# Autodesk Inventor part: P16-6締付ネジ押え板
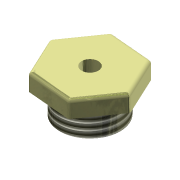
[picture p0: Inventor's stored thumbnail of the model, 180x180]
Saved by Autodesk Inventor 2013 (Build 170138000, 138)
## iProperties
Shininess: 64.0
Length Units: 11269
Angle Units: 11279
Time Units: 11290
Mass Units: 11284
Length Display Precision: 2
Angle Display Precision: 1
Created: 2002-10
Part Number: P16-6締付ネジ押え板
Document SubType Name: ﾓﾃﾞﾘﾝｸﾞ
Designer: 株式会社富士システム
Stock Number: P16-6締付ネジ押え板
Density: 1 g/cm^3
Material: 一般
Density: 0.0
Volumn: 0.0
Area: 0.0
PropertySet Name: Model Information
Control State: 0
Master: False
Checked Out: False
Author: 株式会社富士システム
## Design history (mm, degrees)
sketch "ｽｹｯﾁ1"
  geometry: C1 r 18 at (16.993, -14.869)
  constraints: 1 centre point
  dimensions: "d0" = 36 diameter of C1
extrude "押し出し1" new body sketch "ｽｹｯﾁ1" distance "d1" = 15; taper "d2" = 0 deg
sketch "ｽｹｯﾁ2"
  geometry: L1 (11.232, -24.066)-(-15.225, -21.76); L2 (-15.225, -21.76)-(-26.458, 2.305); L3 (-26.458, 2.305)-(-11.232, 24.066); L4 (-11.232, 24.066)-(15.225, 21.76); L5 (15.225, 21.76)-(26.458, -2.305); L6 (26.458, -2.305)-(11.232, -24.066); C1 r 18 at (0, 0) reference; 1 further point
  constraints: 12 end point, 1 coincident, 11 other
  dimensions: "d4" = 23 distance from line of L4 L5.end
extrude "押し出し2" join sketch "ｽｹｯﾁ2" distance "d5" = 10; taper "d6" = 0 deg
feature "ねじ1" dims "d7" = 10, "d8" = 0
sketch "ｽｹｯﾁ3"
  geometry: C1 r 18 at (0, 0) reference; C2 r 5 at (0, 0)
  constraints: 1 centre point, 1 coincident
  dimensions: "d9" = 10 diameter of C2
extrude "押し出し3" cut sketch "ｽｹｯﾁ3" stored distance "d10" = 10; taper "d11" = 0 deg
fillet "ﾌｨﾚｯﾄ1" dims "d12" = 2
node "ソリッド1"
node "ソリッド ボディ"
node "サーフェス ボディ"
